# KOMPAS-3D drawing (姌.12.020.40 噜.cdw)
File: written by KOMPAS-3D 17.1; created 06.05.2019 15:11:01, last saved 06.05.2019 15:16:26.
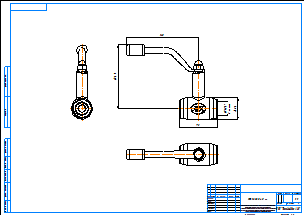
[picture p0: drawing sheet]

Sheet 1: A2, landscape

Title block, sheet 1: name: КШ.12.020.40 рр; material: Внимание! Данный продукт является объектом авторского права ООО «Торговый Дом АДЛ». / Запрещается изменение, копирование, распространение / (в том числе путем копирования на другие сайты и ресурсы в Интернете) / или любое иное использование информации и объектов без предварительного / согласия правообладателя (ООО «Торговый Дом АДЛ»).; scale: 1:1; sheets: 1; organisation: ООО "Торговый дом АДЛ"; sheet format: A2; stored path: C:\Users\tra\Desktop\2д чертежи\Шаровые краны БИВАЛ\КШ_Бивал_серия_11_12\KOMPAS_2D\КШ.12.020.40 рр.cdw

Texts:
  user
Dimensions and other numbers on the sheet: 124,7; 75; 42,4; 3/4"; 2 места; 140; 1:1; 1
